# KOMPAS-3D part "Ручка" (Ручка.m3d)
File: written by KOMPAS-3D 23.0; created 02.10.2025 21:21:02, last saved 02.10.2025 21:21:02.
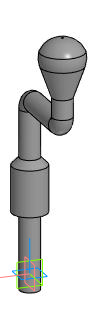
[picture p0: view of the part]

Document properties: Автор: Inspektor_Kot; Полное имя файла: I:\Autodesk Inventor Projects\ИМ-ИТ ЦД\Вариант 9\Ручка.m3d

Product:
- Part/product: Ручка

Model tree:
1. Эскиз:1  (with: Элемент выдавливания:1)
2. Элемент выдавливания:1
     Расстояние 1 = 348
3. Эскиз:2  (with: Элемент вращения:1)
4. Элемент выдавливания:2
     Расстояние 1 = 90
5. Фаска:1  (with: Элемент выдавливания:2)
     Угол = 45; Длина 1 = 15; Длина 2 = 15
6. Эскиз:3  (with: Элемент выдавливания:1)
7. Элемент вращения:1
     Угол 1 = 90
8. Элемент выдавливания:3  (with: Элемент вращения:1)
     Расстояние 1 = 129
9. Эскиз:4  (with: Элемент выдавливания:3)
10. Элемент вращения:2
     Угол 1 = 90
11. Элемент выдавливания:4  (with: Элемент вращения:2)
     Расстояние 1 = 38
12. Элемент выдавливания:5  (with: Элемент выдавливания:4)
     Расстояние 1 = 38; Угол 1 = 20
13. Элемент выдавливания:6  (with: Элемент выдавливания:5)
     Расстояние 1 = 38; Угол 1 = 20
14. Элемент выдавливания:7  (with: Элемент выдавливания:6)
     Расстояние 1 = 38; Угол 1 = 20
15. Скругление:1  (with: Элемент выдавливания:7)
     Радиус = 45
16. Скругление:2  (with: Элемент выдавливания:7)
     Радиус = 45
